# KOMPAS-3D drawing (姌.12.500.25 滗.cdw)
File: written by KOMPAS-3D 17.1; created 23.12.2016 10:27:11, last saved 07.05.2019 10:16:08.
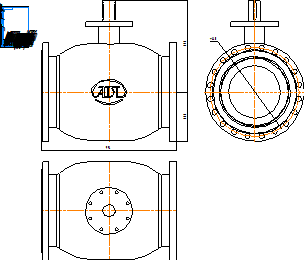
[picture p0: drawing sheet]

Sheet 1: A4, portrait

Title block, sheet 1: name: КШ.12.500.25 фф; material: Внимание! Данный продукт является объектом авторского права ООО «Торговый Дом АДЛ». / Запрещается изменение, копирование, распространение / (в том числе путем копирования на другие сайты и ресурсы в Интернете) / или любое иное использование информации и объектов без предварительного / согласия правообладателя (ООО «Торговый Дом АДЛ»).; sheets: 1; organisation: ООО "Торговый дом АДЛ"; sheet format: A4; stored path: C:\Users\tra\Desktop\2д чертежи\Шаровые краны БИВАЛ\КШ_Бивал_серия_11_12\KOMPAS_2D\КШ.12.500.25 фф.cdw

Views: Вид 1, Проекционный вид 2, Проекционный вид 3
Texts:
  Klimkovich
  ADL
Dimensions and other numbers on the sheet: 996; 673; 365; 660; 1:1; 1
